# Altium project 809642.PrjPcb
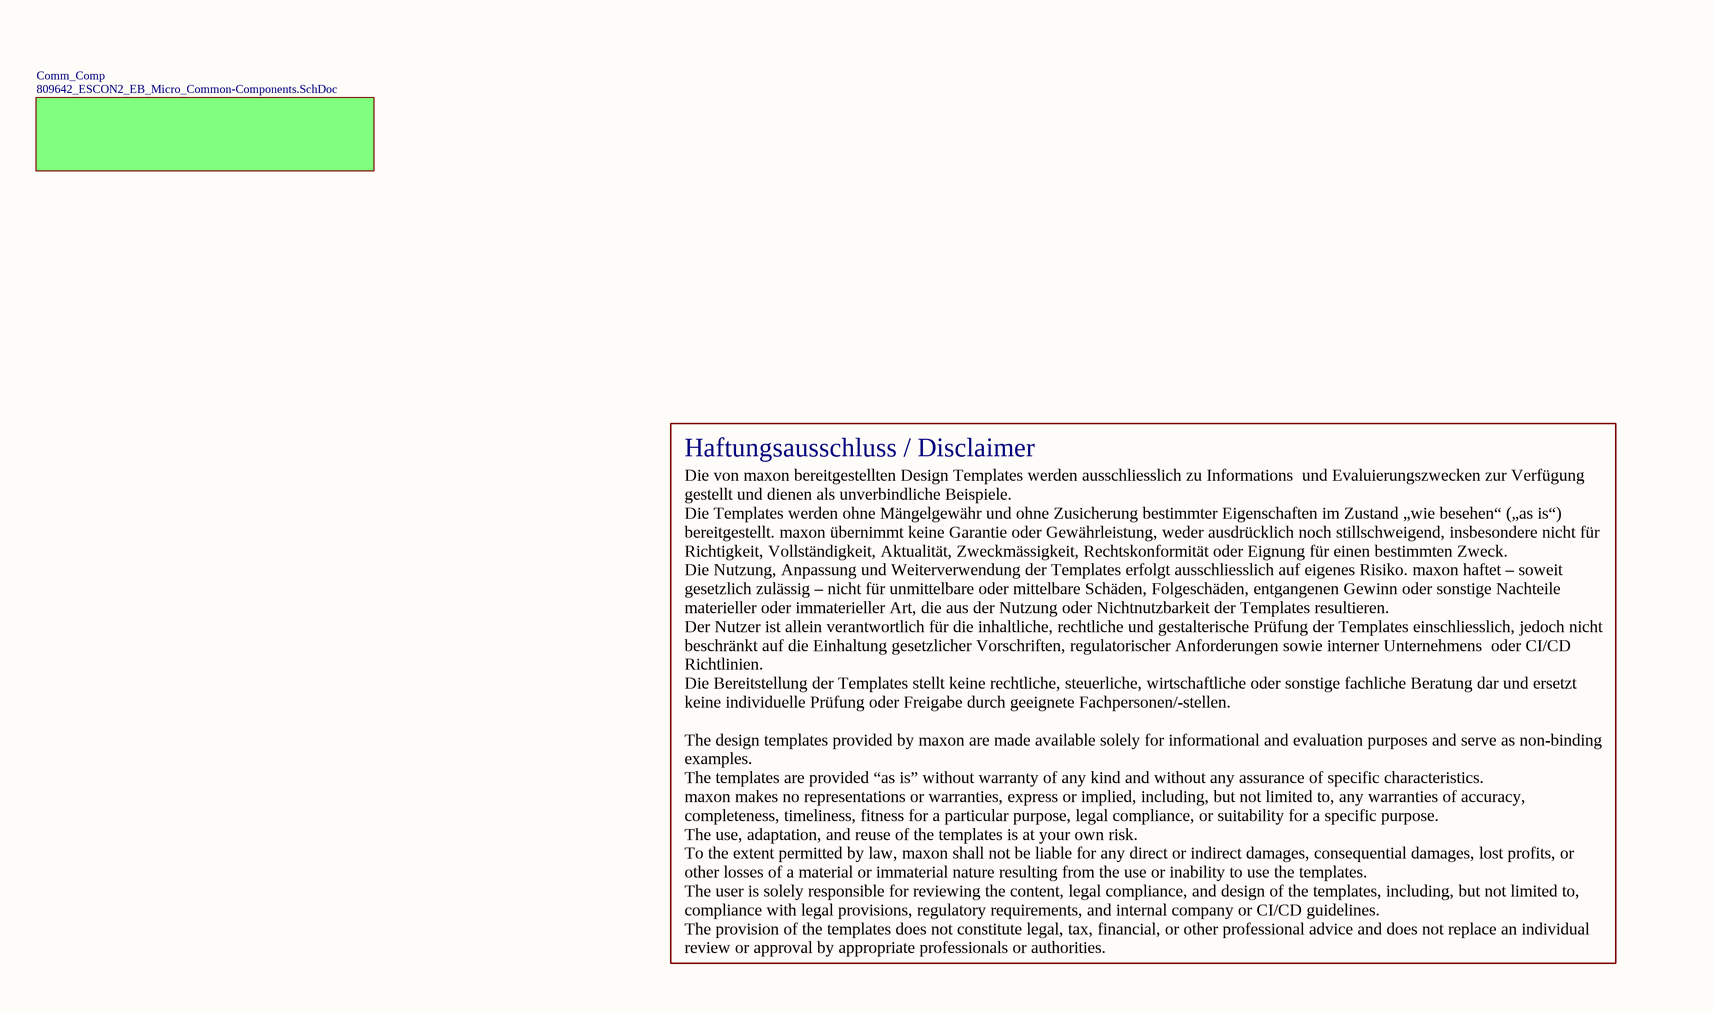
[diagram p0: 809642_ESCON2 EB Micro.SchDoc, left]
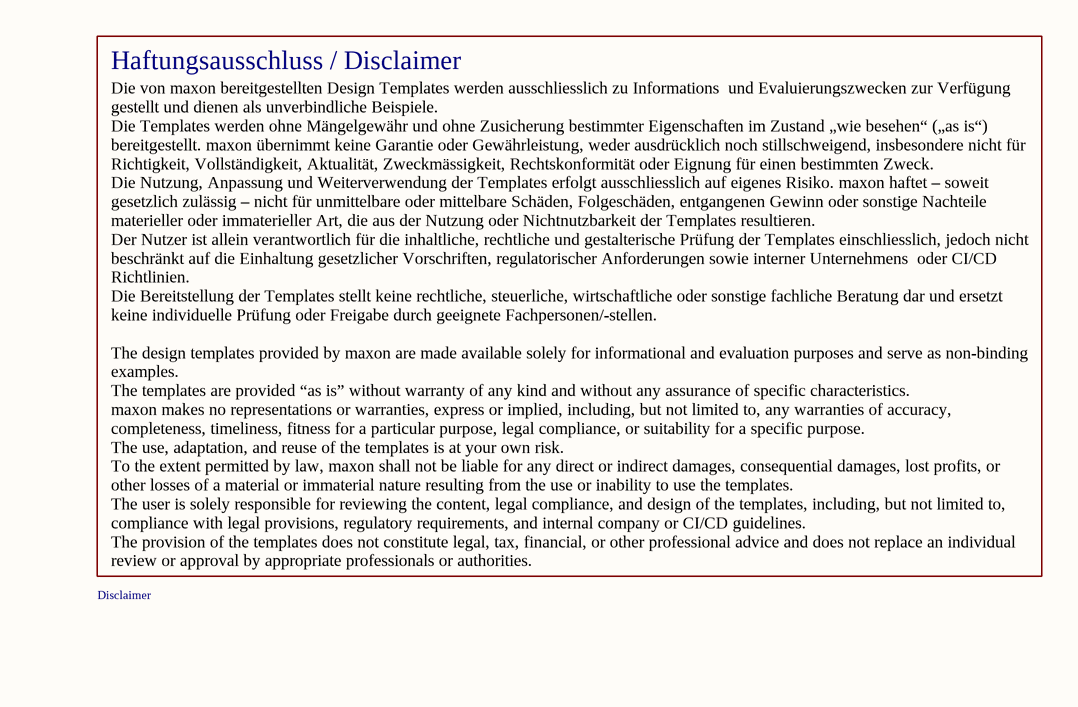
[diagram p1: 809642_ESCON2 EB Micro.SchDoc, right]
CO_no: A100028401; Department: CCMC; PCB_raw: 809642-03
3 sheets, 194 parts. Net scope: hierarchical (ports join the sheet entries above them; power ports are global).
Board file: ESCON2 EB Micro.PcbDoc
Sheets:
  809642_ESCON2 EB Micro.SchDoc
    Comm_Comp = 809642_ESCON2_EB_Micro_Common-Components.SchDoc
      Micro_Comp = 809642_ESCON2_EB_Micro_Micro-Components.SchDoc

## Sheet 809642_ESCON2 EB Micro.SchDoc
size A3; SheetNumber: 1; SheetTotal: 3; Created: MMAGHIN; Modified: MMAGHIN; Reviewed: MMAGWAH; CreatedDate: 10.07.2023; ReviewedDate: 26.03.2024; ModifiedDate1: 26.03.2024

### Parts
(Parts that share a designator on the sheet are numbered #1, #2 ... from top to bottom, then left to right.)
*#1  Disclaimer  (graphical)
*#2  Disclaimer  (value not drawn)  (graphical)

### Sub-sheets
Comm_Comp = 809642_ESCON2_EB_Micro_Common-Components.SchDoc: no entries

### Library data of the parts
*#1 *#2 = CMP-002918-3: Disclaimer Text according to IFS-Doc:13538260

## Sheet 809642_ESCON2_EB_Micro_Common-Components.SchDoc
size A3; SheetNumber: 2; SheetTotal: 3; Created: MMAGHIN; Modified: MMAGHIN; Reviewed: MMAGWAH; CreatedDate: 10.07.2023; ReviewedDate: 26.03.2024; ModifiedDate1: 26.03.2024
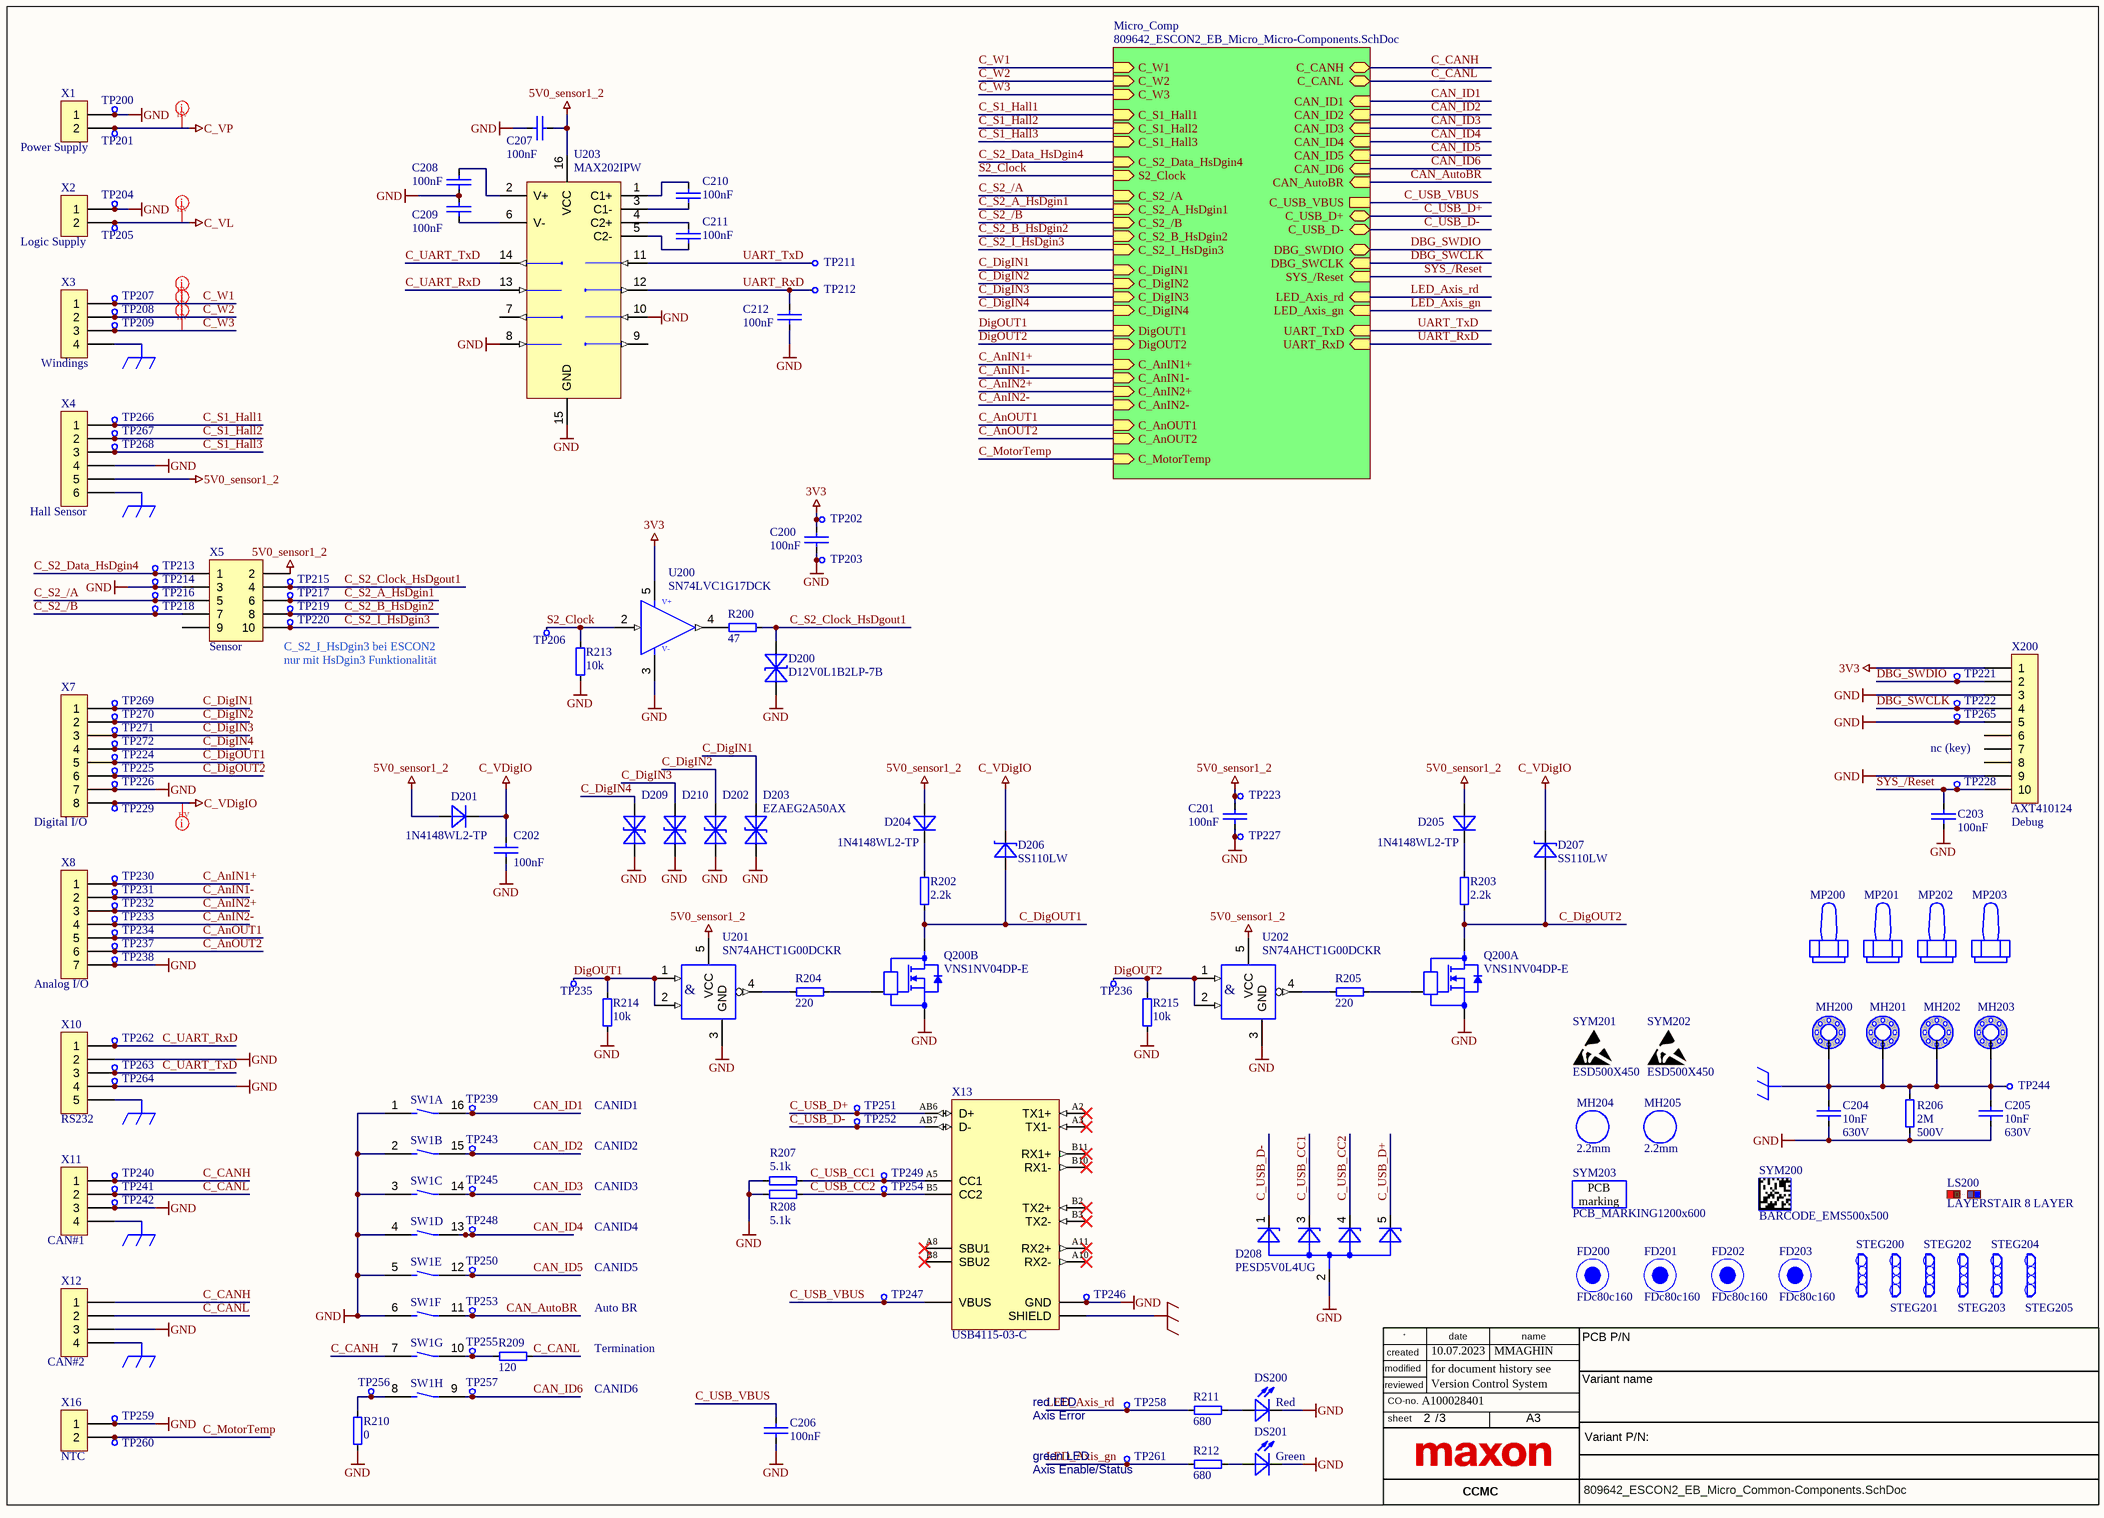
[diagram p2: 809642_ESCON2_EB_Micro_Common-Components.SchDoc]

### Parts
C200  value 100nF  [CAPC100X50X70L25N]  (hidden comment: 0402 100nF)
C201  value 100nF  [CAPC100X50X70L25N]  (hidden comment: 0402 100nF)
C202  value 100nF  [CAPC160X80X100L35N]  (hidden comment: 0603 100nF)
C203  value 100nF  [CAPC100X50X70L25N]  (hidden comment: 0402 100nF)
C204  value 10nF  Maximum Working Voltage: 630V  [CAPC200X125X150L47N]  (hidden comment: C0805C103KBRACAUTO)
C205  value 10nF  Maximum Working Voltage: 630V  [CAPC200X125X150L47N]  (hidden comment: C0805C103KBRACAUTO)
C206  value 100nF  [CAPC160X80X100L35N]  (hidden comment: 0603 100nF)
C207  value 100nF  [CAPC100X50X70L25N]  (hidden comment: 0402 100nF)
C208  value 100nF  [CAPC100X50X70L25N]  (hidden comment: 0402 100nF)
C209  value 100nF  [CAPC100X50X70L25N]  (hidden comment: 0402 100nF)
C210  value 100nF  [CAPC100X50X70L25N]  (hidden comment: 0402 100nF)
C211  value 100nF  [CAPC100X50X70L25N]  (hidden comment: 0402 100nF)
C212  value 100nF  [CAPC100X50X70L25N]  (hidden comment: 0402 100nF)
D200  D12V0L1B2LP-7B  [DIONPDFN2_102X60X60L25X50N]
D201  1N4148WL2-TP  [DIODFN2_102X60X60L25X50N]
D202  EZAEG2A50AX  [DIONPC105X53X43L26N]
D203  EZAEG2A50AX  [DIONPC105X53X43L26N]  (value not drawn)
D204  1N4148WL2-TP  [DIODFN2_102X60X60L25X50N]
D205  1N4148WL2-TP  [DIODFN2_102X60X60L25X50N]
D206  SS110LW  [SODFL359X170X143L65X95N]
D207  SS110LW  [SODFL359X170X143L65X95N]
D208  PESD5V0L4UG  [SOT23-5P65_210X110L28X20N]
D209  EZAEG2A50AX  [DIONPC105X53X43L26N]  (value not drawn)
D210  EZAEG2A50AX  [DIONPC105X53X43L26N]  (value not drawn)
DS200  Color(s): Red  [LEDSC80X160X90L45N_RED]  (hidden comment: 598-8010-107F)
DS201  Color(s): Green  [LEDSC80X160X90L45N_GREEN]  (hidden comment: 598-8070-107F)
FD200  FDc80c160  [FIDUCIAL_c80_c160]  (no BOM)
FD201  FDc80c160  [FIDUCIAL_c80_c160]  (no BOM)
FD202  FDc80c160  [FIDUCIAL_c80_c160]  (no BOM)
FD203  FDc80c160  [FIDUCIAL_c80_c160]  (no BOM)
LS200  LAYERSTAIR 8 LAYER  [8LS400X50w/oLETTERS_KEEPOUT]  (no BOM)
MH200  MTGNPH400A900V8H40_Snap-In_Spacer  [MTGNPH400A900V8H40_Snap-In_Spacer]  (value not drawn)  (no BOM)
MH201  MTGNPH400A900V8H40_Snap-In_Spacer  [MTGNPH400A900V8H40_Snap-In_Spacer]  (value not drawn)  (no BOM)
MH202  MTGNPH400A900V8H40_Snap-In_Spacer  [MTGNPH400A900V8H40_Snap-In_Spacer]  (value not drawn)  (no BOM)
MH203  MTGNPH400A900V8H40_Snap-In_Spacer  [MTGNPH400A900V8H40_Snap-In_Spacer]  (value not drawn)  (no BOM)
MH204  Diameter: 2.2mm  [MTGNPH220]  (hidden comment: MTGNPH220_NPTH)  (no BOM)
MH205  Diameter: 2.2mm  [MTGNPH220]  (hidden comment: MTGNPH220_NPTH)  (no BOM)
MP200  973100365  [WURTH_973100365]  (value not drawn)
MP201  973100365  [WURTH_973100365]  (value not drawn)
MP202  973100365  [WURTH_973100365]  (value not drawn)
MP203  973100365  [WURTH_973100365]  (value not drawn)
Q200  VNS1NV04DP-E  [SOIC8P127_490X599X175L83X41N]  (parts A,B of 2)
R200  value 47  [RESC100X52X40L22N]  (hidden comment: 0402 47R)
R202  value 2.2k  [RESC100X52X40L22N]  (hidden comment: 0402 2.2k)
R203  value 2.2k  [RESC100X52X40L22N]  (hidden comment: 0402 2.2k)
R204  value 220  [RESC100X52X40L22N]  (hidden comment: 0402 220R)
R205  value 220  [RESC100X52X40L22N]  (hidden comment: 0402 220R)
R206  value 2M  Maximum Working Voltage: 500V  [RESC320X160X90L47N]  (hidden comment: 1206 2M 500V)
R207  value 5.1k  [RESC100X52X40L22N]  (hidden comment: 0402 5.1k)
R208  value 5.1k  [RESC100X52X40L22N]  (hidden comment: 0402 5.1k)
R209  value 120  [RESC200X125X84L35N]  (hidden comment: 0805 120R)
R210  value 0  [RESC100X52X40L22N]  (hidden comment: 0402 0)
R211  value 680  [RESC100X52X40L22N]  (hidden comment: 0402 680R)
R212  value 680  [RESC100X52X40L22N]  (hidden comment: 0402 680R)
R213  value 10k  [RESC100X52X40L22N]  (hidden comment: 0402 10k)
R214  value 10k  [RESC100X52X40L22N]  (hidden comment: 0402 10k)
R215  value 10k  [RESC100X52X40L22N]  (hidden comment: 0402 10k)
STEG200  Steg400X90_7Hole  [Steg_400X90_7Hole]  (value not drawn)  (no BOM)
STEG201  Steg400X90_7Hole  [Steg_400X90_7Hole]  (value not drawn)  (no BOM)
STEG202  Steg400X90_7Hole  [Steg_400X90_7Hole]  (value not drawn)  (no BOM)
STEG203  Steg400X90_7Hole  [Steg_400X90_7Hole]  (value not drawn)  (no BOM)
STEG204  Steg400X90_7Hole  [Steg_400X90_7Hole]  (value not drawn)  (no BOM)
STEG205  Steg400X90_7Hole  [Steg_400X90_7Hole]  (value not drawn)  (no BOM)
SW1  DHN-08F-T-V  [SOIC16P127_1139X671X151L61X41N]  (value not drawn)  (parts A,B,C,D,E,F,G,H of 8)
SYM200  BARCODE_EMS500x500  [BARCODE_EMS_500x500]  (no BOM)
SYM201  ESD500X450  [ESD_copper_small]  (no BOM)
SYM202  ESD500X450  [ESD_copper_small]  (no BOM)
SYM203  PCB_MARKING1200x600  [MARKING_PCB_1200x600]  (no BOM)
TP200  TPc120  [TESTPOINT_c120]  (value not drawn)  (no BOM)
TP201  TPc120  [TESTPOINT_c120]  (value not drawn)  (no BOM)
TP202  TPc120  [TESTPOINT_c120]  (value not drawn)  (no BOM)
TP203  TPc120  [TESTPOINT_c120]  (value not drawn)  (no BOM)
TP204  TPc120  [TESTPOINT_c120]  (value not drawn)  (no BOM)
TP205  TPc120  [TESTPOINT_c120]  (value not drawn)  (no BOM)
TP206  TPc120  [TESTPOINT_c120]  (value not drawn)  (no BOM)
TP207  TPc120  [TESTPOINT_c120]  (value not drawn)  (no BOM)
TP208  TPc120  [TESTPOINT_c120]  (value not drawn)  (no BOM)
TP209  TPc120  [TESTPOINT_c120]  (value not drawn)  (no BOM)
TP211  TPc120  [TESTPOINT_c120]  (value not drawn)  (no BOM)
TP212  TPc120  [TESTPOINT_c120]  (value not drawn)  (no BOM)
TP213  TPc120  [TESTPOINT_c120]  (value not drawn)  (no BOM)
TP214  TPc120  [TESTPOINT_c120]  (value not drawn)  (no BOM)
TP215  TPc120  [TESTPOINT_c120]  (value not drawn)  (no BOM)
TP216  TPc120  [TESTPOINT_c120]  (value not drawn)  (no BOM)
TP217  TPc120  [TESTPOINT_c120]  (value not drawn)  (no BOM)
TP218  TPc120  [TESTPOINT_c120]  (value not drawn)  (no BOM)
TP219  TPc120  [TESTPOINT_c120]  (value not drawn)  (no BOM)
TP220  TPc120  [TESTPOINT_c120]  (value not drawn)  (no BOM)
TP221  TPc120  [TESTPOINT_c120]  (value not drawn)  (no BOM)
TP222  TPc120  [TESTPOINT_c120]  (value not drawn)  (no BOM)
TP223  TPc120  [TESTPOINT_c120]  (value not drawn)  (no BOM)
TP224  TPc120  [TESTPOINT_c120]  (value not drawn)  (no BOM)
TP225  TPc120  [TESTPOINT_c120]  (value not drawn)  (no BOM)
TP226  TPc120  [TESTPOINT_c120]  (value not drawn)  (no BOM)
TP227  TPc120  [TESTPOINT_c120]  (value not drawn)  (no BOM)
TP228  TPc120  [TESTPOINT_c120]  (value not drawn)  (no BOM)
TP229  TPc120  [TESTPOINT_c120]  (value not drawn)  (no BOM)
TP230  TPc120  [TESTPOINT_c120]  (value not drawn)  (no BOM)
TP231  TPc120  [TESTPOINT_c120]  (value not drawn)  (no BOM)
TP232  TPc120  [TESTPOINT_c120]  (value not drawn)  (no BOM)
TP233  TPc120  [TESTPOINT_c120]  (value not drawn)  (no BOM)
TP234  TPc120  [TESTPOINT_c120]  (value not drawn)  (no BOM)
TP235  TPc120  [TESTPOINT_c120]  (value not drawn)  (no BOM)
TP236  TPc120  [TESTPOINT_c120]  (value not drawn)  (no BOM)
TP237  TPc120  [TESTPOINT_c120]  (value not drawn)  (no BOM)
TP238  TPc120  [TESTPOINT_c120]  (value not drawn)  (no BOM)
TP239  TPc120  [TESTPOINT_c120]  (value not drawn)  (no BOM)
TP240  TPc120  [TESTPOINT_c120]  (value not drawn)  (no BOM)
TP241  TPc120  [TESTPOINT_c120]  (value not drawn)  (no BOM)
TP242  TPc120  [TESTPOINT_c120]  (value not drawn)  (no BOM)
TP243  TPc120  [TESTPOINT_c120]  (value not drawn)  (no BOM)
TP244  TPc120  [TESTPOINT_c120]  (value not drawn)  (no BOM)
TP245  TPc120  [TESTPOINT_c120]  (value not drawn)  (no BOM)
TP246  TPc120  [TESTPOINT_c120]  (value not drawn)  (no BOM)
TP247  TPc120  [TESTPOINT_c120]  (value not drawn)  (no BOM)
TP248  TPc120  [TESTPOINT_c120]  (value not drawn)  (no BOM)
TP249  TPc120  [TESTPOINT_c120]  (value not drawn)  (no BOM)
TP250  TPc120  [TESTPOINT_c120]  (value not drawn)  (no BOM)
TP251  TPc120  [TESTPOINT_c120]  (value not drawn)  (no BOM)
TP252  TPc120  [TESTPOINT_c120]  (value not drawn)  (no BOM)
TP253  TPc120  [TESTPOINT_c120]  (value not drawn)  (no BOM)
TP254  TPc120  [TESTPOINT_c120]  (value not drawn)  (no BOM)
TP255  TPc120  [TESTPOINT_c120]  (value not drawn)  (no BOM)
TP256  TPc120  [TESTPOINT_c120]  (value not drawn)  (no BOM)
TP257  TPc120  [TESTPOINT_c120]  (value not drawn)  (no BOM)
TP258  TPc120  [TESTPOINT_c120]  (value not drawn)  (no BOM)
TP259  TPc120  [TESTPOINT_c120]  (value not drawn)  (no BOM)
TP260  TPc120  [TESTPOINT_c120]  (value not drawn)  (no BOM)
TP261  TPc120  [TESTPOINT_c120]  (value not drawn)  (no BOM)
TP262  TPc120  [TESTPOINT_c120]  (value not drawn)  (no BOM)
TP263  TPc120  [TESTPOINT_c120]  (value not drawn)  (no BOM)
TP264  TPc120  [TESTPOINT_c120]  (value not drawn)  (no BOM)
TP265  TPc120  [TESTPOINT_c120]  (value not drawn)  (no BOM)
TP266  TPc120  [TESTPOINT_c120]  (value not drawn)  (no BOM)
TP267  TPc120  [TESTPOINT_c120]  (value not drawn)  (no BOM)
TP268  TPc120  [TESTPOINT_c120]  (value not drawn)  (no BOM)
TP269  TPc120  [TESTPOINT_c120]  (value not drawn)  (no BOM)
TP270  TPc120  [TESTPOINT_c120]  (value not drawn)  (no BOM)
TP271  TPc120  [TESTPOINT_c120]  (value not drawn)  (no BOM)
TP272  TPc120  [TESTPOINT_c120]  (value not drawn)  (no BOM)
U200  SN74LVC1G17DCK  [SOT23-5P65_210X110L28X20N]
U201  SN74AHCT1G00DCKR  [SOT23-5P65_210X110L28X20N]
U202  SN74AHCT1G00DCKR  [SOT23-5P65_210X110L28X20N]
U203  MAX202IPW  [SOP16P65_500X640X120L83X24N]
X1  39281023  [MOLEX_460150202]  (value not drawn)
X2  39281023  [MOLEX_460150202]  (value not drawn)
X3  39281043  [MOLEX_460150402]  (value not drawn)
X4  430450612  [MOLEX_ 430450612]  (value not drawn)
X5  52601-S10-8LF  [AMPHENOL_52601-S10-8LF]  (value not drawn)
X7  5025840860  [MOLEX_5025840860]  (value not drawn)
X8  5025840760  [MOLEX_5025840760]  (value not drawn)
X10  RS232  [MOLEX_5025840560]
X11  5025840460  [MOLEX_5025840460]  (value not drawn)
X12  5025840460  [MOLEX_5025840460]  (value not drawn)
X13  USB4115-03-C  [GTC_USB4115-03-C]
X16  430450212  [MOLEX_ 430450212]  (value not drawn)
X200  AXT410124  [PANASONIC_AXT410124]

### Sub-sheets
Micro_Comp = 809642_ESCON2_EB_Micro_Micro-Components.SchDoc: C_W1 (in), C_W2 (in), C_W3 (in), C_S1_Hall1 (in), C_S1_Hall2 (in), C_S1_Hall3 (in), C_S2_Data_HsDgin4 (in), S2_Clock (in), C_S2_/A (in), C_S2_A_HsDgin1 (in), C_S2_/B (in), C_S2_B_HsDgin2 (in), C_S2_I_HsDgin3 (in), C_DigIN1 (in), C_DigIN2 (in), C_DigIN3 (in), C_DigIN4 (in), DigOUT1 (in), DigOUT2 (in), C_AnIN1+ (in), C_AnIN1- (in), C_AnIN2+ (in), C_AnIN2- (in), C_AnOUT1 (in), C_AnOUT2 (in), C_CANH (bidir), C_CANL (bidir), CAN_ID1 (in), CAN_ID2 (in), CAN_ID3 (in), CAN_ID4 (in), CAN_ID5 (in), CAN_ID6 (in), CAN_AutoBR (in), C_USB_VBUS, C_USB_D+ (bidir), C_USB_D- (bidir), DBG_SWDIO (bidir), DBG_SWCLK (in), SYS_/Reset (in), UART_TxD (in), UART_RxD (in), LED_Axis_rd (in), LED_Axis_gn (in), C_MotorTemp (in)

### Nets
3V3: C200.2 TP202.1 U200.5(VCC) X200.1
5V0_sensor1_2: C201.2 C207.1 D201.2(A) D204.2(A) D205.2(A) TP223.1 U201.5(VCC) U202.5(VCC) U203.16(VCC) X4.5 X5.2
C_VDigIO: C202.2 D201.1(C) D206.1(C) D207.1(C) TP229.1 X7.8
C_VL: TP205.1 X2.2
C_VP: TP201.1 X1.2
GND: C200.1 C201.1 C202.1 C203.1 C204.1 C205.1 C206.1 C207.2 C208.1 C209.2 C212.1 D200.1 D202.1 D203.1 D208.2(A) D209.1 D210.1 DS200.1(C) DS201.1(C) Q200.1(S1) Q200.3(S2) R206.1 R207.2 R208.2 R210.1 R213.1 R214.1 R215.1 SW1.1 SW1.2 SW1.3 SW1.4 SW1.5 SW1.6 TP200.1 TP203.1 TP204.1 TP214.1 TP226.1 TP227.1 TP238.1 TP242.1 TP246.1 TP259.1 TP264.1 TP265.1 U200.3(GND) U201.3(GND) U202.3(GND) U203.8(RIN2) U203.10(DIN2) U203.15(GND) X1.1 X2.1 X4.4 X5.3 X7.7 X8.7 X10.2 X10.4 X11.3 X12.3 X13.AB112(GND) X16.1 X200.3 X200.5 X200.9
SGND: C204.2 C205.2 MH200.1 MH201.1 MH202.1 MH203.1 R206.2 TP244.1 X3.4 X4.6 X10.5 X11.4 X12.4 X13.SHIELD
C_AnIN1+: TP230.1 X8.1 ; sheet Micro_Comp/C_AnIN1+
C_AnIN1-: TP231.1 X8.2 ; sheet Micro_Comp/C_AnIN1-
C_AnIN2+: TP232.1 X8.3 ; sheet Micro_Comp/C_AnIN2+
C_AnIN2-: TP233.1 X8.4 ; sheet Micro_Comp/C_AnIN2-
C_AnOUT1: TP234.1 X8.5 ; sheet Micro_Comp/C_AnOUT1
C_AnOUT2: TP237.1 X8.6 ; sheet Micro_Comp/C_AnOUT2
C_CANH: SW1.7 TP240.1 X11.1 X12.1 ; sheet Micro_Comp/C_CANH
C_CANL: R209.2 TP241.1 X11.2 X12.2 ; sheet Micro_Comp/C_CANL
C_DigIN1: D203.2 TP269.1 X7.1 ; sheet Micro_Comp/C_DigIN1
C_DigIN2: D202.2 TP270.1 X7.2 ; sheet Micro_Comp/C_DigIN2
C_DigIN3: D210.2 TP271.1 X7.3 ; sheet Micro_Comp/C_DigIN3
C_DigIN4: D209.2 TP272.1 X7.4 ; sheet Micro_Comp/C_DigIN4
C_DigOUT1: D206.2(A) Q200.5(D2) R202.1 TP224.1 X7.5
C_DigOUT2: D207.2(A) Q200.6(D1) R203.1 TP225.1 X7.6
C_MotorTemp: TP260.1 X16.2 ; sheet Micro_Comp/C_MotorTemp
C_S1_Hall1: TP266.1 X4.1 ; sheet Micro_Comp/C_S1_Hall1
C_S1_Hall2: TP267.1 X4.2 ; sheet Micro_Comp/C_S1_Hall2
C_S1_Hall3: TP268.1 X4.3 ; sheet Micro_Comp/C_S1_Hall3
C_S2_/A: TP216.1 X5.5 ; sheet Micro_Comp/C_S2_/A
C_S2_/B: TP218.1 X5.7 ; sheet Micro_Comp/C_S2_/B
C_S2_A_HsDgin1: TP217.1 X5.6 ; sheet Micro_Comp/C_S2_A_HsDgin1
C_S2_B_HsDgin2: TP219.1 X5.8 ; sheet Micro_Comp/C_S2_B_HsDgin2
C_S2_Clock_HsDgout1: D200.2 R200.2 TP215.1 X5.4
C_S2_Data_HsDgin4: TP213.1 X5.1 ; sheet Micro_Comp/C_S2_Data_HsDgin4
C_S2_I_HsDgin3: TP220.1 X5.10 ; sheet Micro_Comp/C_S2_I_HsDgin3
C_UART_RxD: TP262.1 U203.13(RIN1) X10.1
C_UART_TxD: TP263.1 U203.14(DOUT1) X10.3
C_USB_CC1: D208.3 R207.1 TP249.1 X13.A5(CC1)
C_USB_CC2: D208.4 R208.1 TP254.1 X13.B5(CC2)
C_USB_D+: D208.5 TP251.1 X13.AB6(D+) ; sheet Micro_Comp/C_USB_D+
C_USB_D-: D208.1 TP252.1 X13.AB7(D-) ; sheet Micro_Comp/C_USB_D-
C_USB_VBUS: C206.2 TP247.1 X13.AB49(VBUS) ; sheet Micro_Comp/C_USB_VBUS
C_W1: TP207.1 X3.1 ; sheet Micro_Comp/C_W1
C_W2: TP208.1 X3.2 ; sheet Micro_Comp/C_W2
C_W3: TP209.1 X3.3 ; sheet Micro_Comp/C_W3
CAN_AutoBR: SW1.11 TP253.1 ; sheet Micro_Comp/CAN_AutoBR
CAN_ID1: SW1.16 TP239.1 ; sheet Micro_Comp/CAN_ID1
CAN_ID2: SW1.15 TP243.1 ; sheet Micro_Comp/CAN_ID2
CAN_ID3: SW1.14 TP245.1 ; sheet Micro_Comp/CAN_ID3
CAN_ID4: SW1.13 TP248.1 ; sheet Micro_Comp/CAN_ID4
CAN_ID5: SW1.12 TP250.1 ; sheet Micro_Comp/CAN_ID5
CAN_ID6: SW1.9 TP257.1 ; sheet Micro_Comp/CAN_ID6
DBG_SWCLK: TP222.1 X200.4 ; sheet Micro_Comp/DBG_SWCLK
DBG_SWDIO: TP221.1 X200.2 ; sheet Micro_Comp/DBG_SWDIO
DigOUT1: R214.2 TP235.1 U201.1(inA) U201.2(inB) ; sheet Micro_Comp/DigOUT1
DigOUT2: R215.2 TP236.1 U202.1(inA) U202.2(inB) ; sheet Micro_Comp/DigOUT2
LED_Axis_gn: R212.1 TP261.1 ; sheet Micro_Comp/LED_Axis_gn
LED_Axis_rd: R211.1 TP258.1 ; sheet Micro_Comp/LED_Axis_rd
S2_Clock: R213.2 TP206.1 U200.2(inA) ; sheet Micro_Comp/S2_Clock
SYS_/Reset: C203.2 TP228.1 X200.10 ; sheet Micro_Comp/SYS_/Reset
UART_RxD: C212.2 TP212.1 U203.12(ROUT1) ; sheet Micro_Comp/UART_RxD
UART_TxD: TP211.1 U203.11(DIN1) ; sheet Micro_Comp/UART_TxD
NetC208_2: C208.2 U203.2(V+)
NetC209_1: C209.1 U203.6(V-)
NetC210_1: C210.1 U203.1(C1+)
NetC210_2: C210.2 U203.3(C1-)
NetC211_1: C211.1 U203.4(C2+)
NetC211_2: C211.2 U203.5(C2-)
NetD204_1: D204.1(C) R202.2
NetD205_1: D205.1(C) R203.2
NetDS200_2: DS200.2(A) R211.2
NetDS201_2: DS201.2(A) R212.2
NetQ200_2: Q200.2(IN1) R205.2
NetQ200_4: Q200.4(IN2) R204.2
NetR200_1: R200.1 U200.4(outY)
NetR204_1: R204.1 U201.4(outY)
NetR205_1: R205.1 U202.4(outY)
NetR209_1: R209.1 SW1.10 TP255.1
NetR210_2: R210.2 SW1.8 TP256.1

Not connected (* = marked no-connect by the designer): U203 7(DOUT2) 9(ROUT2); X5 9; X13 A2(TX1+)* A3(TX1-)* A8(SBU1)* A10(RX2-)* A11(RX2+)* B2(TX2+)* B3(TX2-)* B8(SBU2)* B10(RX1-)* B11(RX1+)*; X200 6 7 8

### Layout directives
net class HV: C_VDigIO, C_VL, C_VP, C_W1, C_W2, C_W3

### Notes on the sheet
- Power Supply
- Logic Supply
- (near X3) Windings
- (near X4) Hall Sensor
- (near X5) Sensor
- C_S2_I_HsDgin3 bei ESCON2
- nur mit HsDgin3 Funktionalität
- nc (key)
- Digital I/O
- (near X200) Debug
- (near X8) Analog I/O
- CANID1
- CANID2
- CANID3
- (near X11) CAN#1
- CANID4
- CANID5
- Auto BR
- (near X12) CAN#2
- CANID6
- Termination
- (near X16) NTC
- red LED
- Axis Error
- green LED
- Axis Enable/Status

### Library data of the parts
C200 C201 C203 C207-C212 = CMP-000709-3: 100nF X7R >=16V 20%; Part Number: Ceramic, 0402, 100nF, 20%, >=16V, X7R, @, Soft Termination: N, -55°C to 125°C; Manufacturer: X; Maximum Working Voltage: 16V; Soft Termination: N; Case (Metric): 1005
C202 C206 = CMP-000703-3: 100nF X7R >=100V 20%; Part Number: Ceramic, 0603, 100nF, 20%, >=100V, X7R, @, Soft Termination: N, -55°C to 125°C; Manufacturer: X; Soft Termination: N; Case (Metric): 1608; Maximum Working Voltage: 100V
C204 C205 = CMP-000937-4: 10nF X7R >=630V 20%; Manufacturer: Murata; Dielectric Withstanding Voltage: > 850V 1sec; Case (Metric): 2012; Soft Termination: N
D200 = CMP-001106-5: Transient Voltage Suppressor Diode, 12V V(RWM), Bidirectional, 100W, 1 Element, SOD-882/DFN1006; Manufacturer: Diodes; Element Configuration: Single; Breakdown Voltage: 13V; Polarity: Bipolar
D201 D204 D205 = CMP-000606-13: Diode Switching, >=70V, >=150mA, SOD882/DFN1006/0402/SOD-923F; Manufacturer: MCC; Polarity: Unipolar; Recovery time: 4ns; Reverse Voltage: 70V; Element Configuration: Single; RMS Current: 150mA
D202 D203 D209 D210 = CMP-000066-17: Transient Voltage Suppressor Diode, 30V V(RWM), Bidirectional, ESD, 1 Element, 0402; Manufacturer: Panasonic; Element Configuration: Single; Polarity: Bipolar
D206 D207 = CMP-000633-9: Schottky Diode, >=90V, >=1A, SOD-123FL/SOD-123W; Manufacturer: Taiwan Semiconductor; RMS Current: 1A; Polarity: Unipolar; Reverse Voltage: 90V; Element Configuration: Single
D208 = CMP-000635-10: Transient Voltage Suppressor Diode, 4-Line, 5V V(RWM), Unidirectional, 30W, 4 Element , SOT353/SC-88A; Manufacturer: Nexperia; Min Breakdown Voltage: 6.46V; Nummber of Pins: 5; Element Configuration: Array; Common Anode; Max Junction Temperature: 150°C; Polarity: Unipolar; Breakdown Voltage: 6.8V; Nummber of Elements: 4; Max Breakdown Voltage: 7.14V; Clamping Voltage: 12V
DS200 = CMP-000723-6: Single Color Chip LED, red, 0603; Manufacturer: Dialight; Luminous Intensity: >5mcd@20mA; Wavelength: 617-640nm
DS201 = CMP-000722-5: Single Color Chip LED, green, 0603; Manufacturer: Dialight; Luminous Intensity: >5mcd@20mA; Wavelength: 564...575nm
FD200-FD203 = CMP-000010-5: Fiducial, Global, Round; 0.80 mm D, 1.60 mm Clearance
LS200 = CMP-001088-3: Layer Stair 8 Layer
MH200-MH203 = CMP-001801-1: Mounting Hole, Non-Plated; 9.00 mm Clearance, 4.00 mm Hole (with 8 vias), for 4mm Dia. Snap-In Spacer; pin to pad: 1>2+3+4+5+6+7+8+9; Metric screw: 4mm Dia Snap-In Spacer; Wave: X
MH204 MH205 = CMP-001004-5: Mounting Hole, Non-Plated; 0.00 mm Clearance, 2.20 mm Hole
MP200-MP203 = CMP-001759-4: WA-SNTI Plastic Spacer Stud, D=4.0mm, L=10mm, M3, SW=6; Min PCB Thickness: 1.8mm; Max PCB Thickness: 2.1mm; Mounting Hole Diameter: 4.00mm; Stand-Off Height: 10mm; Stand-Off Outside Size: SW6; Connection Style PCB Side: Snap; Connection Diameter PCB Side: 4.0mm; Connection Style Far Side: Female; Connection Length Far Side: 5mm; Stand-Off Outside Style: Hex; Connection Length PCB Side: 9.5mm
Q200 = CMP-001108-5: N-Channel MOSFET, Self Protected, 36V, 0.5ohm, SO-8; pin to pad: 5>5+6 6>7+8; Manufacturer: ST Microelectronics; Element Configuration: N-CH, Self Protected
R200 = CMP-000161-11: 47R 1% 62.5mW 100ppm; Part Number: Thick-Film, 0402, 47, 1%, 62.5mW@70°C, 50V, 100ppm, -55°C to 155°C; Manufacturer: X; Max Junction Temperature: 155°C; AECQ: N; Case (Metric): 1050; Power Rating Temperature: 70°C; Maximum Working Voltage: 50V; Maximum Overload Voltage: 100V
R202 R203 = CMP-000197-11: 2.2k 1% 62.5mW 100ppm; Part Number: Thick-Film, 0402, 2.2k, 1%, 62.5mW@70°C, 50V, 100ppm, -55°C to 155°C; Manufacturer: X; Max Junction Temperature: 155°C; AECQ: N; Case (Metric): 1050; Power Rating Temperature: 70°C; Maximum Working Voltage: 50V; Maximum Overload Voltage: 100V
R204 R205 = CMP-000173-11: 220R 1% 62.5mW 100ppm; Part Number: Thick-Film, 0402, 220, 1%, 62.5mW@70°C, 50V, 100ppm, -55°C to 155°C; Manufacturer: X; Max Junction Temperature: 155°C; AECQ: N; Case (Metric): 1050; Power Rating Temperature: 70°C; Maximum Working Voltage: 50V; Maximum Overload Voltage: 100V
R206 = CMP-000935-4: 2M 5% 250mW 200ppm >=500V; Manufacturer: X; Part Number: Thick-Film, 1206, 2M, 5%, 250mW@70°C, 500V, 200ppm, -55°C to 155°C; AECQ: N; Case (Metric): 3216; Maximum Overload Voltage: 1kV; Power Rating Temperature: 70°C; Max Junction Temperature: 155°C
R207 R208 = CMP-000206-11: 5.1k 1% 62.5mW 100ppm; Part Number: Thick-Film, 0402, 5.1k, 1%, 62.5mW@70°C, 50V, 100ppm, -55°C to 155°C; Manufacturer: X; Max Junction Temperature: 155°C; AECQ: N; Case (Metric): 1050; Power Rating Temperature: 70°C; Maximum Working Voltage: 50V; Maximum Overload Voltage: 100V
R209 = CMP-000325-10: 120R 1% 125mW 100ppm; Part Number: Thick-Film, 0805, 120, 1%, 125mW@70°C, 150V, 100ppm, -55°C to 155°C; Manufacturer: X; Max Junction Temperature: 155°C; AECQ: N; Case (Metric): 2012; Power Rating Temperature: 70°C; Maximum Working Voltage: 150V; Maximum Overload Voltage: 300V
R210 = CMP-000466-10: 0R Jumper; Part Number: Thick-Film, 0402, 0, -55°C to 155°C; Manufacturer: X; Case (Metric): 1050; RMS Current: 1A; Maximum Overload Voltage: 100V; Max Junction Temperature: 155°C; Maximum Working Voltage: 50V
R211 R212 = CMP-000185-11: 680R 1% 62.5mW 100ppm; Part Number: Thick-Film, 0402, 680, 1%, 62.5mW@70°C, 50V, 100ppm, -55°C to 155°C; Manufacturer: X; Max Junction Temperature: 155°C; AECQ: N; Case (Metric): 1050; Power Rating Temperature: 70°C; Maximum Working Voltage: 50V; Maximum Overload Voltage: 100V
R213-R215 = CMP-000492-11: 10k 1% 62.5mW 100ppm; Part Number: Thick-Film, 0402, 10k, 1%, 62.5mW@70°C, 50V, 100ppm, -55°C to 155°C; Manufacturer: X; Max Junction Temperature: 155°C; AECQ: N; Case (Metric): 1050; Power Rating Temperature: 70°C; Maximum Working Voltage: 50V; Maximum Overload Voltage: 100V
STEG200-STEG205 = CMP-000007-5: Breakaway tabs; 4.00 mm L X 0.90 mm W, 7 Hole
SW1 = CMP-001031-3: Slide Dip Switch, 8 Switches, 0.025A, 24VDC, SMD; Manufacturer: Diptronics
SYM200 = CMP-001233-2: Barcode EMS; 5.0 x 5.0 mm
SYM201 SYM202 = CMP-000018-5: ESD-Sign; 5.0 mm L X 4.5 mm W
SYM203 = CMP-001854-7: PCB Marking; 12.0 x 6.0 mm
TP200-TP209 TP211-TP272 = CMP-000014-7: Test Point; 1 pin, 1.20 mm D
U200 = CMP-001041-6: Single buffer with Schmitt-Trigger inputs; Manufacturer: Texas Instruments; AECQ: N; Max Supply Voltage: 5.5V; Min Supply Voltage: 1.65V
U201 U202 = CMP-002037-1: Single, 2-Input NAND Gate, 5V; Min Supply Voltage: 4.5V; Max Supply Voltage: 5.5V
U203 = CMP-000646-4: RS-232 Line Transceiver, Dual channel 120kbps , 5.0V, TSSOP16; Manufacturer: Texas instruments; Max Supply Voltage: 5.5V; Min Supply Voltage: 4.5V
X1 X2 = CMP-001018-6: Mini-Fit Jr. Vertical Header, 4.20mm Pitch, Dual Row, 2 Circuits, without Snap-in Plastic Peg PCB Lock, Tin, Natural; Number of Contacts: 2; Operating Voltage: 600V; Operating Current: 9A; System: Connector
X3 = CMP-001016-8: Mini-Fit Jr. Vertical Header, 4.20mm Pitch, Dual Row, 4 Circuits, without Snap-in Plastic Peg PCB Lock, Tin, Natural; Operating Current: 9A; Operating Voltage: 600V; Number of Contacts: 4; System: Connector
X4 = CMP-001098-6: Micro-Fit 3.0 Vertical Header, 3.00mm Pitch, Dual Row, 6 Circuits, with PCB Polarizing Peg, Black; Manufacturer: Molex; Operating Voltage: 600V; Number of Contacts: 6; Operating Current: 8.5A
X5 = CMP-001165-3: Header, 2.54mm Pitch, Dual Row, SMT, Vertical, 10 Circuits; Manufacturer: Amphenol; Operating Voltage: 500V; Number of Contacts: 10; Operating Current: 3A
X7 = CMP-001014-7: 1.50mm Pitch, CLIK-Mate PCB Receptacle, Single Row, Surface Mount, Tin Plating, Positive Lock, with Pick-and-Place Polyimide Tape, 8 Circuits, Beige; Manufacturer: Molex; Number of Contacts: 8; Operating Current: 2A; Operating Voltage: 100V
X8 = CMP-001015-7: 1.50mm Pitch, CLIK-Mate PCB Receptacle, Single Row, Surface Mount, Tin Plating, Positive Lock, with Pick-and-Place Polyimide Tape, 7 Circuits, Beige; Manufacturer: Molex; Operating Voltage: 100V; Operating Current: 2A; Number of Contacts: 7
X10 = CMP-001023-6: 1.50mm Pitch, CLIK-Mate PCB Receptacle, Single Row, Surface Mount, Tin Plating, Positive Lock, with Pick-and-Place Polyimide Tape, 5 Circuits, Beige; Manufacturer: Molex; Operating Current: 2A; Operating Voltage: 100V; Number of Contacts: 5
X11 X12 = CMP-001170-6: 1.50mm Pitch, CLIK-Mate PCB Receptacle, Single Row, Surface Mount, Tin Plating, Positive Lock, with Pick-and-Place Polyimide Tape, 4 Circuits, Beige; Manufacturer: Molex; Number of Contacts: 4; Operating Voltage: 100V; Operating Current: 2A
X13 = CMP-001110-9: USB Type C, SHLD, 24poles, vertical; pin to pad: AB6>A6+B6 AB7>A7+B7 AB49>A4+A9+B4+B9 AB112>B1+A12+B12+A1 SHIELD>S1+S2+S3+S4; Manufacturer: GTC
X16 = CMP-001107-4: Micro-Fit 3.0 Vertical Header, 3.00mm Pitch, Dual Row, 2 Circuits, with PCB Polarizing Peg, Black; Manufacturer: Molex; Operating Voltage: 600V; Number of Contacts: 2; Operating Current: 8.5A
X200 = CMP-001083-11: Board to Board Connector, 2*5 pole, SMD, 0.4mm pitch, 1.5mm stacking Height; Manufacturer: Panasonic; Number of Contacts: 10; Operating Current: 300mA; Operating Voltage: 60V

## Sheet 809642_ESCON2_EB_Micro_Micro-Components.SchDoc
size A3; SheetNumber: 3; SheetTotal: 3; Created: MMAGHIN; Modified: MMAGHIN; Reviewed: MMAGWAH; CreatedDate: 10.07.2023; ReviewedDate: 26.03.2024; ModifiedDate1: 26.03.2024
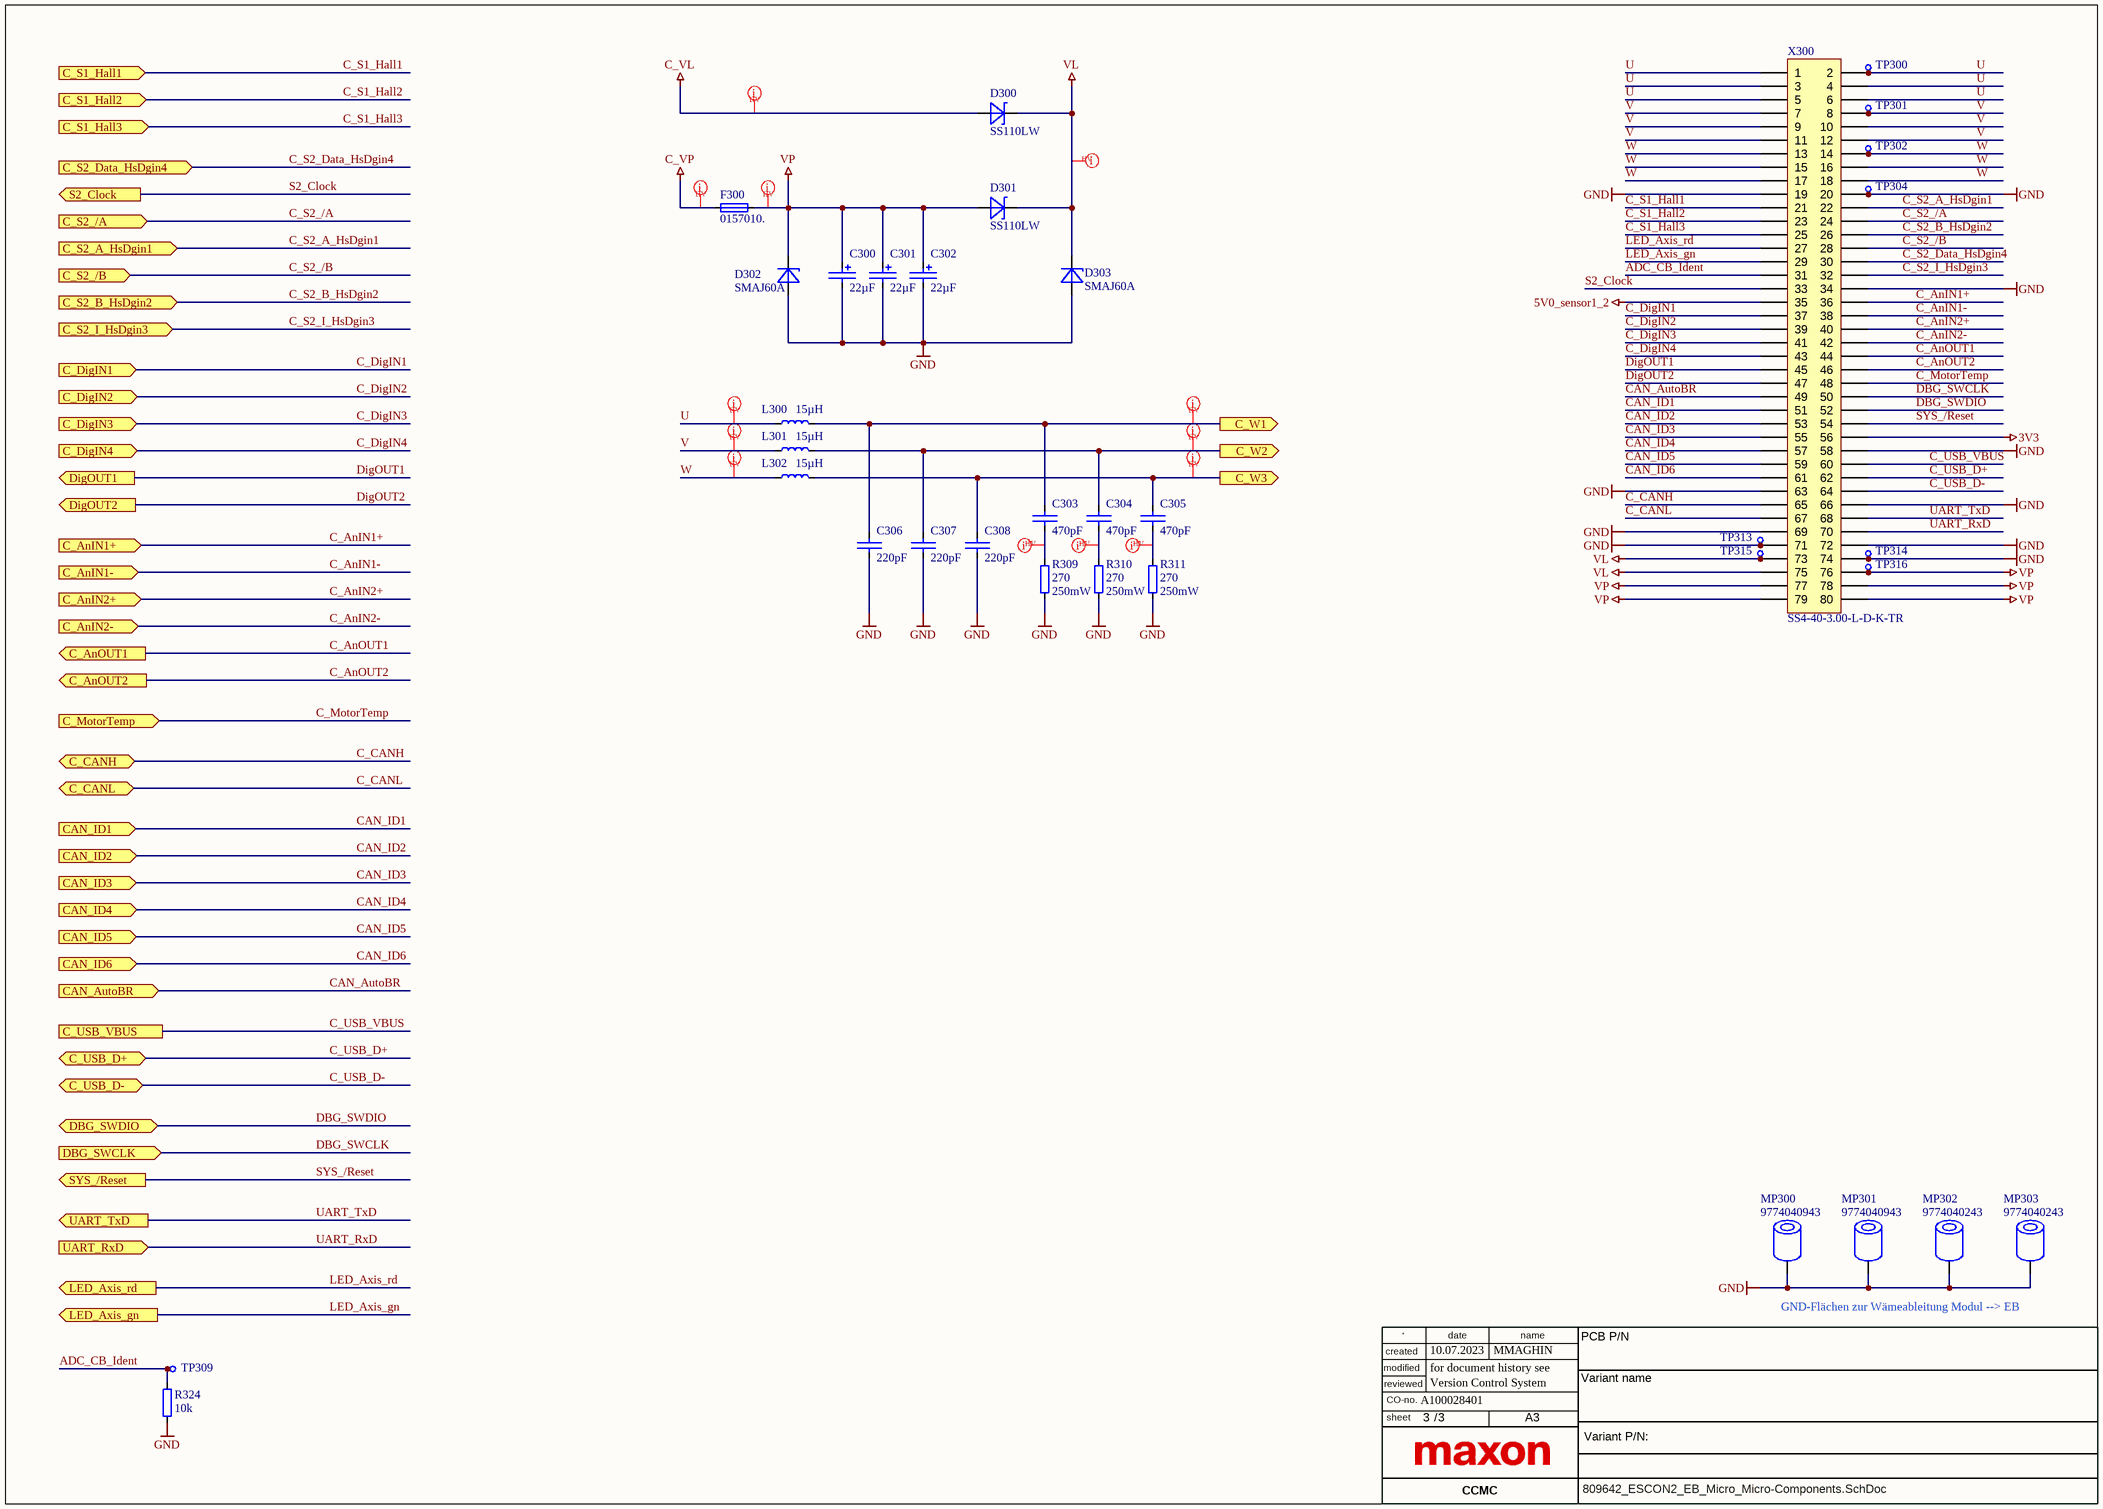
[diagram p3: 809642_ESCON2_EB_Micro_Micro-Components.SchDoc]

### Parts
C300  value 22µF  [PANASONIC_F_VIB]  (hidden comment: EEHZA1K220P)
C301  value 22µF  [PANASONIC_F_VIB]  (hidden comment: EEHZA1K220P)
C302  value 22µF  [PANASONIC_F_VIB]  (hidden comment: EEHZA1K220P)
C303  value 470pF  [CAPC160X80X100L35N]  (hidden comment: 0603 470p)
C304  value 470pF  [CAPC160X80X100L35N]  (hidden comment: 0603 470p)
C305  value 470pF  [CAPC160X80X100L35N]  (hidden comment: 0603 470p)
C306  value 220pF  [CAPC160X80X100L35N]  (hidden comment: 0603 220pF)
C307  value 220pF  [CAPC160X80X100L35N]  (hidden comment: 0603 220pF)
C308  value 220pF  [CAPC160X80X100L35N]  (hidden comment: 0603 220pF)
D300  SS110LW  [SODFL359X170X143L65X95N]
D301  SS110LW  [SODFL359X170X143L65X95N]
D302  SMAJ60A  [DIOM519X260X262L114X145N]
D303  SMAJ60A  [DIOM519X260X262L114X145N]
F300  0157010.  [FUSC650X370X403L148N]
L300  value 15µH  [INDDFN2_1200X1200X1020L255X500N]  (hidden comment: 7447709150)
L301  value 15µH  [INDDFN2_1200X1200X1020L255X500N]  (hidden comment: 7447709150)
L302  value 15µH  [INDDFN2_1200X1200X1020L255X500N]  (hidden comment: 7447709150)
MP300  9774040943  [WURTH_9774040943_NPTH]
MP301  9774040943  [WURTH_9774040943_NPTH]
MP302  9774040243  [WURTH_9774040243_NPTH]
MP303  9774040243  [WURTH_9774040243_NPTH]
R309  value 270  Power Rating: 250mW  [RESC200X125X84L35N]  (hidden comment: 0805 270R)
R310  value 270  Power Rating: 250mW  [RESC200X125X84L35N]  (hidden comment: 0805 270R)
R311  value 270  Power Rating: 250mW  [RESC200X125X84L35N]  (hidden comment: 0805 270R)
R324  value 10k  [RESC100X52X40L22N]  (hidden comment: 0402 10k)
TP300  TPc120  [TESTPOINT_c120]  (value not drawn)  (no BOM)
TP301  TPc120  [TESTPOINT_c120]  (value not drawn)  (no BOM)
TP302  TPc120  [TESTPOINT_c120]  (value not drawn)  (no BOM)
TP304  TPc120  [TESTPOINT_c120]  (value not drawn)  (no BOM)
TP309  TPc120  [TESTPOINT_c120]  (value not drawn)  (no BOM)
TP313  TPc120  [TESTPOINT_c120]  (value not drawn)  (no BOM)
TP314  TPc120  [TESTPOINT_c120]  (value not drawn)  (no BOM)
TP315  TPc120  [TESTPOINT_c120]  (value not drawn)  (no BOM)
TP316  TPc120  [TESTPOINT_c120]  (value not drawn)  (no BOM)
X300  SS4-40-3.00-L-D-K-TR  [SAMTEC_SS4-40-3.00-L-D-K-TR]

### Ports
C_AnIN1+ (in), C_AnIN1- (in), C_AnIN2+ (in), C_AnIN2- (in), C_AnOUT1 (out), C_AnOUT2 (out), C_CANH (bidir), C_CANL (bidir), C_DigIN1 (in), C_DigIN2 (in), C_DigIN3 (in), C_DigIN4 (in), C_MotorTemp (in), C_S1_Hall1 (in), C_S1_Hall2 (in), C_S1_Hall3 (in), C_S2_/A (in), C_S2_/B (in), C_S2_A_HsDgin1 (in), C_S2_B_HsDgin2 (in), C_S2_Data_HsDgin4 (in), C_S2_I_HsDgin3 (in), C_USB_D+ (bidir), C_USB_D- (bidir), C_USB_VBUS, C_W1 (out), C_W2 (out), C_W3 (out), CAN_AutoBR (in), CAN_ID1 (in), CAN_ID2 (in), CAN_ID3 (in), CAN_ID4 (in), CAN_ID5 (in), CAN_ID6 (in), DBG_SWCLK (in), DBG_SWDIO (bidir), DigOUT1 (out), DigOUT2 (out), LED_Axis_gn (out), LED_Axis_rd (out), S2_Clock (out), SYS_/Reset (out), UART_RxD (in), UART_TxD (out)

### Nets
3V3: X300.56
5V0_sensor1_2: X300.35
C_VL: D300.2(A)
C_VP: F300.1
GND: C300.2(-) C301.2(-) C302.2(-) C306.1 C307.1 C308.1 D302.2(A) D303.2(A) MP300.1 MP301.1 MP302.1 MP303.1 R309.1 R310.1 R311.1 R324.1 TP304.1 TP313.1 TP314.1 X300.19 X300.20 X300.34 X300.58 X300.63 X300.66 X300.69 X300.71 X300.72 X300.74
VL: D300.1(C) D301.1(C) D303.1(C) TP315.1 X300.73 X300.75
VP: C300.1(+) C301.1(+) C302.1(+) D301.2(A) D302.1(C) F300.2 TP316.1 X300.76 X300.77 X300.78 X300.79 X300.80
ADC_CB_Ident: R324.2 TP309.1 X300.31
C_AnIN1+: X300.36 ; port C_AnIN1+
C_AnIN1-: X300.38 ; port C_AnIN1-
C_AnIN2+: X300.40 ; port C_AnIN2+
C_AnIN2-: X300.42 ; port C_AnIN2-
C_AnOUT1: X300.44 ; port C_AnOUT1
C_AnOUT2: X300.46 ; port C_AnOUT2
C_CANH: X300.65 ; port C_CANH
C_CANL: X300.67 ; port C_CANL
C_DigIN1: X300.37 ; port C_DigIN1
C_DigIN2: X300.39 ; port C_DigIN2
C_DigIN3: X300.41 ; port C_DigIN3
C_DigIN4: X300.43 ; port C_DigIN4
C_MotorTemp: X300.48 ; port C_MotorTemp
C_S1_Hall1: X300.21 ; port C_S1_Hall1
C_S1_Hall2: X300.23 ; port C_S1_Hall2
C_S1_Hall3: X300.25 ; port C_S1_Hall3
C_S2_/A: X300.24 ; port C_S2_/A
C_S2_/B: X300.28 ; port C_S2_/B
C_S2_A_HsDgin1: X300.22 ; port C_S2_A_HsDgin1
C_S2_B_HsDgin2: X300.26 ; port C_S2_B_HsDgin2
C_S2_Data_HsDgin4: X300.30 ; port C_S2_Data_HsDgin4
C_S2_I_HsDgin3: X300.32 ; port C_S2_I_HsDgin3
C_USB_D+: X300.62 ; port C_USB_D+
C_USB_D-: X300.64 ; port C_USB_D-
C_USB_VBUS: X300.60 ; port C_USB_VBUS
C_W1: C303.2 C306.2 L300.2 ; port C_W1
C_W2: C304.2 C307.2 L301.2 ; port C_W2
C_W3: C305.2 C308.2 L302.2 ; port C_W3
CAN_AutoBR: X300.49 ; port CAN_AutoBR
CAN_ID1: X300.51 ; port CAN_ID1
CAN_ID2: X300.53 ; port CAN_ID2
CAN_ID3: X300.55 ; port CAN_ID3
CAN_ID4: X300.57 ; port CAN_ID4
CAN_ID5: X300.59 ; port CAN_ID5
CAN_ID6: X300.61 ; port CAN_ID6
DBG_SWCLK: X300.50 ; port DBG_SWCLK
DBG_SWDIO: X300.52 ; port DBG_SWDIO
DigOUT1: X300.45 ; port DigOUT1
DigOUT2: X300.47 ; port DigOUT2
LED_Axis_gn: X300.29 ; port LED_Axis_gn
LED_Axis_rd: X300.27 ; port LED_Axis_rd
S2_Clock: X300.33 ; port S2_Clock
SYS_/Reset: X300.54 ; port SYS_/Reset
U: L300.1 TP300.1 X300.1 X300.2 X300.3 X300.4 X300.5 X300.6
UART_RxD: X300.70 ; port UART_RxD
UART_TxD: X300.68 ; port UART_TxD
V: L301.1 TP301.1 X300.7 X300.8 X300.9 X300.10 X300.11 X300.12
W: L302.1 TP302.1 X300.13 X300.14 X300.15 X300.16 X300.17 X300.18
NetC303_1: C303.1 R309.2
NetC304_1: C304.1 R310.2
NetC305_1: C305.1 R311.2

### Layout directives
net class HV: C_VL, C_VP, C_W1, C_W2, C_W3, NetC303_1, NetC304_1, NetC305_1, U, V, VL, VP, W

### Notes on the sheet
- GND-Flächen zur Wämeableitung Modul --> EB

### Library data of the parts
C300-C302 = CMP-000967-5: Polymer Hybrid Elco 22uF >=80V 20% D=8mm, H=10.5mm; Manufacturer: Panasonic; Vibration proof: N; Ripple Current: 1.55A; Endurance: >=10'000h @105°C; Maximum Working Voltage: 80V; Case (Metric): G, D=8mm, H=10.5mm
C303-C305 = CMP-001011-3: 470p C0G/NP0/X7R >=100V 20%; Manufacturer: X; Part Number: Ceramic, 0603, 470pF, 20%, >=100V, C0G/NP0/X7R, @, Soft Termination: N, -55°C to 125°C; Maximum Working Voltage: 100V; Case (Metric): 1608; Soft Termination: N
C306-C308 = CMP-001012-4: 220pF C0G/NP0/X7R >=100V 20%; Manufacturer: X; Part Number: Ceramic, 0603, 220pF, 20%, >=100V, C0G/NP0/X7R, @, Soft Termination: N, -55°C to 125°C; Case (Metric): 1608; Maximum Working Voltage: 100V; Soft Termination: N
D300 D301 = CMP-000633-9: as D206 on sheet 809642_ESCON2_EB_Micro_Common-Components
D302 D303 = CMP-001103-4: Transient Voltage Suppressor Diode, 60V V(RWM), Unidirectional, 400W, 1 Element, DO-214AC; Manufacturer: X; Element Configuration: Single; Clamping Voltage: 96.8V; Breakdown Voltage: 66.7V; Polarity: Unipolar
F300 = CMP-001757-3: Electric Fuse, Very Fast Blow, 10A, 125VAC, 125VDC, 35A (IR), Clip Assembly; Manufacturer: Littelfuse; Maximum Working Voltage: 125V; Melting Integral: 26.46
L300-L302 = CMP-001747-7: Inductor Shielded, 15uH, 20%, I_RMS>6.5A, I_Sat>9.8A, R<26mOhm, 12.0x12.0mm, Height<=10mm; Polarity: N; Case (Metric): 0; RMS Current: 5.7A; Saturation Current: 9.8A
MP300 MP301 = CMP-001744-2: WA-SMST SMT Steel Spacer with through hole Ø 2.25mm, L=4mm; Manufacturer: Wurth; Metric screw: M2
MP302 MP303 = CMP-001745-2: WA-SMST SMT Steel Spacer with internal Thread M2, L=4mm; Manufacturer: Wurth
R309-R311 = CMP-001764-2: 270R 1% 250mW 100ppm; Part Number: Thick-Film, 0805, 270, 1%, 250mW@70°C, 150V, 100ppm, -55°C to 155°C; Power Rating Temperature: 70°C; Max Junction Temperature: 155°C; Case (Metric): 2012; Maximum Working Voltage: 150V; Anti-Sulfur: N; Maximum Overload Voltage: 300V
R324 = CMP-000492-11: as R213 on sheet 809642_ESCON2_EB_Micro_Common-Components
TP300-TP302 TP304 TP309 TP313-TP316 = CMP-000014-7: Test Point; 1 pin, 1.20 mm D
X300 = CMP-001746-7: SS4 0.40 mm Micro Blade & Beam Ultra Fine Pitch Socket, 80 poles; Manufacturer: Samtec; Number of Contacts: 80; Operating Current: 1.6A; Operating Voltage: 155V; System: Connector

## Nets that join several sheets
3V3: 809642_ESCON2_EB_Micro_Common-Components (C200.2 TP202.1 U200.5 X200.1), 809642_ESCON2_EB_Micro_Micro-Components (X300.56)
5V0_sensor1_2: 809642_ESCON2_EB_Micro_Common-Components (11 pins), 809642_ESCON2_EB_Micro_Micro-Components (X300.35)
C_VL: 809642_ESCON2_EB_Micro_Common-Components (TP205.1 X2.2), 809642_ESCON2_EB_Micro_Micro-Components (D300.2)
C_VP: 809642_ESCON2_EB_Micro_Common-Components (TP201.1 X1.2), 809642_ESCON2_EB_Micro_Micro-Components (F300.1)
GND: 809642_ESCON2_EB_Micro_Common-Components (67 pins), 809642_ESCON2_EB_Micro_Micro-Components (29 pins)
C_AnIN1+: 809642_ESCON2_EB_Micro_Common-Components (TP230.1 X8.1), 809642_ESCON2_EB_Micro_Micro-Components (X300.36)
C_AnIN1-: 809642_ESCON2_EB_Micro_Common-Components (TP231.1 X8.2), 809642_ESCON2_EB_Micro_Micro-Components (X300.38)
C_AnIN2+: 809642_ESCON2_EB_Micro_Common-Components (TP232.1 X8.3), 809642_ESCON2_EB_Micro_Micro-Components (X300.40)
C_AnIN2-: 809642_ESCON2_EB_Micro_Common-Components (TP233.1 X8.4), 809642_ESCON2_EB_Micro_Micro-Components (X300.42)
C_AnOUT1: 809642_ESCON2_EB_Micro_Common-Components (TP234.1 X8.5), 809642_ESCON2_EB_Micro_Micro-Components (X300.44)
C_AnOUT2: 809642_ESCON2_EB_Micro_Common-Components (TP237.1 X8.6), 809642_ESCON2_EB_Micro_Micro-Components (X300.46)
C_CANH: 809642_ESCON2_EB_Micro_Common-Components (SW1.7 TP240.1 X11.1 X12.1), 809642_ESCON2_EB_Micro_Micro-Components (X300.65)
C_CANL: 809642_ESCON2_EB_Micro_Common-Components (R209.2 TP241.1 X11.2 X12.2), 809642_ESCON2_EB_Micro_Micro-Components (X300.67)
C_DigIN1: 809642_ESCON2_EB_Micro_Common-Components (D203.2 TP269.1 X7.1), 809642_ESCON2_EB_Micro_Micro-Components (X300.37)
C_DigIN2: 809642_ESCON2_EB_Micro_Common-Components (D202.2 TP270.1 X7.2), 809642_ESCON2_EB_Micro_Micro-Components (X300.39)
C_DigIN3: 809642_ESCON2_EB_Micro_Common-Components (D210.2 TP271.1 X7.3), 809642_ESCON2_EB_Micro_Micro-Components (X300.41)
C_DigIN4: 809642_ESCON2_EB_Micro_Common-Components (D209.2 TP272.1 X7.4), 809642_ESCON2_EB_Micro_Micro-Components (X300.43)
C_MotorTemp: 809642_ESCON2_EB_Micro_Common-Components (TP260.1 X16.2), 809642_ESCON2_EB_Micro_Micro-Components (X300.48)
C_S1_Hall1: 809642_ESCON2_EB_Micro_Common-Components (TP266.1 X4.1), 809642_ESCON2_EB_Micro_Micro-Components (X300.21)
C_S1_Hall2: 809642_ESCON2_EB_Micro_Common-Components (TP267.1 X4.2), 809642_ESCON2_EB_Micro_Micro-Components (X300.23)
C_S1_Hall3: 809642_ESCON2_EB_Micro_Common-Components (TP268.1 X4.3), 809642_ESCON2_EB_Micro_Micro-Components (X300.25)
C_S2_/A: 809642_ESCON2_EB_Micro_Common-Components (TP216.1 X5.5), 809642_ESCON2_EB_Micro_Micro-Components (X300.24)
C_S2_/B: 809642_ESCON2_EB_Micro_Common-Components (TP218.1 X5.7), 809642_ESCON2_EB_Micro_Micro-Components (X300.28)
C_S2_A_HsDgin1: 809642_ESCON2_EB_Micro_Common-Components (TP217.1 X5.6), 809642_ESCON2_EB_Micro_Micro-Components (X300.22)
C_S2_B_HsDgin2: 809642_ESCON2_EB_Micro_Common-Components (TP219.1 X5.8), 809642_ESCON2_EB_Micro_Micro-Components (X300.26)
C_S2_Data_HsDgin4: 809642_ESCON2_EB_Micro_Common-Components (TP213.1 X5.1), 809642_ESCON2_EB_Micro_Micro-Components (X300.30)
C_S2_I_HsDgin3: 809642_ESCON2_EB_Micro_Common-Components (TP220.1 X5.10), 809642_ESCON2_EB_Micro_Micro-Components (X300.32)
C_USB_D+: 809642_ESCON2_EB_Micro_Common-Components (D208.5 TP251.1 X13.AB6), 809642_ESCON2_EB_Micro_Micro-Components (X300.62)
C_USB_D-: 809642_ESCON2_EB_Micro_Common-Components (D208.1 TP252.1 X13.AB7), 809642_ESCON2_EB_Micro_Micro-Components (X300.64)
C_USB_VBUS: 809642_ESCON2_EB_Micro_Common-Components (C206.2 TP247.1 X13.AB49), 809642_ESCON2_EB_Micro_Micro-Components (X300.60)
C_W1: 809642_ESCON2_EB_Micro_Common-Components (TP207.1 X3.1), 809642_ESCON2_EB_Micro_Micro-Components (C303.2 C306.2 L300.2)
C_W2: 809642_ESCON2_EB_Micro_Common-Components (TP208.1 X3.2), 809642_ESCON2_EB_Micro_Micro-Components (C304.2 C307.2 L301.2)
C_W3: 809642_ESCON2_EB_Micro_Common-Components (TP209.1 X3.3), 809642_ESCON2_EB_Micro_Micro-Components (C305.2 C308.2 L302.2)
CAN_AutoBR: 809642_ESCON2_EB_Micro_Common-Components (SW1.11 TP253.1), 809642_ESCON2_EB_Micro_Micro-Components (X300.49)
CAN_ID1: 809642_ESCON2_EB_Micro_Common-Components (SW1.16 TP239.1), 809642_ESCON2_EB_Micro_Micro-Components (X300.51)
CAN_ID2: 809642_ESCON2_EB_Micro_Common-Components (SW1.15 TP243.1), 809642_ESCON2_EB_Micro_Micro-Components (X300.53)
CAN_ID3: 809642_ESCON2_EB_Micro_Common-Components (SW1.14 TP245.1), 809642_ESCON2_EB_Micro_Micro-Components (X300.55)
CAN_ID4: 809642_ESCON2_EB_Micro_Common-Components (SW1.13 TP248.1), 809642_ESCON2_EB_Micro_Micro-Components (X300.57)
CAN_ID5: 809642_ESCON2_EB_Micro_Common-Components (SW1.12 TP250.1), 809642_ESCON2_EB_Micro_Micro-Components (X300.59)
CAN_ID6: 809642_ESCON2_EB_Micro_Common-Components (SW1.9 TP257.1), 809642_ESCON2_EB_Micro_Micro-Components (X300.61)
DBG_SWCLK: 809642_ESCON2_EB_Micro_Common-Components (TP222.1 X200.4), 809642_ESCON2_EB_Micro_Micro-Components (X300.50)
DBG_SWDIO: 809642_ESCON2_EB_Micro_Common-Components (TP221.1 X200.2), 809642_ESCON2_EB_Micro_Micro-Components (X300.52)
DigOUT1: 809642_ESCON2_EB_Micro_Common-Components (R214.2 TP235.1 U201.1 U201.2), 809642_ESCON2_EB_Micro_Micro-Components (X300.45)
DigOUT2: 809642_ESCON2_EB_Micro_Common-Components (R215.2 TP236.1 U202.1 U202.2), 809642_ESCON2_EB_Micro_Micro-Components (X300.47)
LED_Axis_gn: 809642_ESCON2_EB_Micro_Common-Components (R212.1 TP261.1), 809642_ESCON2_EB_Micro_Micro-Components (X300.29)
LED_Axis_rd: 809642_ESCON2_EB_Micro_Common-Components (R211.1 TP258.1), 809642_ESCON2_EB_Micro_Micro-Components (X300.27)
S2_Clock: 809642_ESCON2_EB_Micro_Common-Components (R213.2 TP206.1 U200.2), 809642_ESCON2_EB_Micro_Micro-Components (X300.33)
SYS_/Reset: 809642_ESCON2_EB_Micro_Common-Components (C203.2 TP228.1 X200.10), 809642_ESCON2_EB_Micro_Micro-Components (X300.54)
UART_RxD: 809642_ESCON2_EB_Micro_Common-Components (C212.2 TP212.1 U203.12), 809642_ESCON2_EB_Micro_Micro-Components (X300.70)
UART_TxD: 809642_ESCON2_EB_Micro_Common-Components (TP211.1 U203.11), 809642_ESCON2_EB_Micro_Micro-Components (X300.68)

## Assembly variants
809643: not fitted C212 C302 D202 D203 D209 D210 R210 X200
